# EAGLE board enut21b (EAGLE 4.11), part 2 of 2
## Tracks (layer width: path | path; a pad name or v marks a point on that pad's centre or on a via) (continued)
PE3 (continued)
  Top 0.152: IC1.5 32.01,50.77 37.6,56.36 37.6,70.15 36.86,70.89 J5.42 36.86,72.72 35.54,74.04 35.54,75.41 36.76,76.63 62.06,76.63 63.35,75.33 63.35,71.6 62.67,70.91 62.67,61.54 63.28,60.93 64.72,60.93 65.72,59.93 JP1.5
PE4
  Top 0.152: IC1.6 31.97,51.57 37.22,56.81 37.22,69.92 35.39,71.75 35.39,72.89 34.32,73.96 J5.43
PE5  (via drill 0.4)
  Top 0.152: J5.44 34.32,72.21 36.84,69.69 36.84,57.2 32.01,52.37 IC1.7 29.92,52.37 v29.29,52.93 | v39.5,45.23 38.89,45.23 38.13,44.47 R2.1
  Bottom 0.152: v29.29,52.93 30.74,52.93 38.13,45.54 38.44,45.23 v39.5,45.23
PE6  (via drill 0.4)
  Top 0.152: 32.05,53.17 IC1.8 30.19,53.17 29.67,53.69 28.83,53.69 v28.38,53.23 | 32.05,53.17 36.45,57.58 36.45,69.39 34.55,71.29 33.79,71.29 33.1,71.98 33.1,72.82 31.78,74.14 J5.45 | 32.05,53.17 32.05,53.23
  Bottom 0.152: v28.38,53.23 29.06,53.92 30.51,53.92 36.91,47.52 38.59,47.52 40.42,45.69 40.42,44.78 40.04,44.39 R31*.1
PE7  (via drill 0.4)
  Top 0.152: IC1.9 32.24,53.97 36.07,57.81 36.07,69.16 34.32,70.91 32.95,70.91 | 32.95,70.91 32.92,70.91 | 32.95,70.91 31.78,72.08 J5.46 31.78,72.77 30.51,74.04 30.51,75.41 32.19,77.08 64.88,77.08 66.09,75.86 66.09,68.02 67.09,67.03 v67.09,66.11
  Bottom 0.152: v67.09,66.11 67.09,63.67 66.4,62.99 64.88,62.99 63.82,61.93 JP1.8
PEN\
  Top 0.152: R4.1 33.69,48.26 33,47.57 IC1.1
PF0  (via drill 0.4)
  Top 0.152: IC1.61 v26.83,47.02
  Bottom 0.152: v26.83,47.02 26.83,46.93 26.85,46.91 23.65,43.71 12.15,43.71 6.38,49.48 J6.5
PF1  (via drill 0.4)
  Top 0.152: IC1.60 | IC1.60 | IC1.60 26.01,45.59 v26.01,47.67
  Bottom 0.152: v26.01,47.67 26.01,46.91 23.27,44.17 12.37,44.17 7.65,48.89 7.65,50.72 6.38,51.99 J6.7
PF2  (via drill 0.4)
  Top 0.152: IC1.59 25.23,45.67 v25.23,47.21
  Bottom 0.152: v25.23,47.21 25.23,47.08 25.25,47.06 22.81,44.62 12.6,44.62 8.11,49.12 8.11,53.31 6.89,54.53 6.43,54.53 J6.9
PF3  (via drill 0.4)
  Top 0.152: IC1.58 24.43,45.67 v24.43,47.61
  Bottom 0.152: v24.43,47.61 24.43,47.46 24.41,47.44 24.41,46.91 22.59,45.08 12.83,45.08 8.56,49.35 8.56,55.47 6.91,57.12 J6.11
PF4  (via drill 0.4)
  Top 0.152: 23.63,45.47 | 23.63,45.47 IC1.57 23.65,45.59 23.65,47.19 | 23.63,45.47 23.65,45.46 | 23.65,47.19 23.65,47.21 | 23.65,47.19 v23.63,47.17 | 23.63,45.47 23.63,41.1 v22.66,40.13 | RN30*.4 20.28,35.19 v20.3,35.1
  Bottom 0.152: v23.63,47.17 23.63,47.01 23.65,46.98 22.2,45.54 13.06,45.54 9.02,49.58 9.02,57.25 6.63,59.63 6.41,59.63 J6.13 | J7.1 11.46,26.64 11.46,28.62 12.07,29.23 15.5,29.23 JP5.8 19.08,32.81 19.08,34.34 19.92,35.17 v20.3,35.1 20.3,37.38 22.66,39.75 v22.66,40.13
PF5  (via drill 0.4)
  Top 0.152: 22.81,47.59 v22.83,47.57 22.83,45.67 IC1.56 22.89,45.52 22.89,41.42 v22.66,41.19 | JP5.10 18.09,33.82 18.09,34.87 18.68,35.46 RN30*.2
  Bottom 0.152: v22.83,47.57 22.83,47.38 22.81,47.37 22.81,46.83 21.98,45.99 13.29,45.99 9.48,49.8 9.48,59.41 6.74,62.15 6.43,62.15 J6.15 | J7.5 14.74,30.45 JP5.10 | JP5.10 18.1,33.81 JP5.10 | JP5.10 18.09,35.94 21.82,39.67 21.82,40.36 v22.66,41.19
PF6  (via drill 0.4)
  Top 0.152: v22.03,47.13 IC1.55 22.05,45.56 v22.05,42.03
  Bottom 0.152: v22.03,47.13 22.03,47.12 21.37,46.45 13.52,46.45 9.94,50.03 9.94,61.56 6.76,64.74 J6.17 | JP5.5 21.21,30.95 21.21,37.46 23.5,39.75 23.5,41.5 22.97,42.03 v22.05,42.03
PF7  (via drill 0.4)
  Top 0.152: IC1.54 | IC1.54 21.23,40.34 22.13,39.44 v26.85,39.44 | IC1.54 v21.23,47.61
  Bottom 0.152: v21.23,47.61 20.53,46.91 13.75,46.91 10.39,50.26 10.39,61.92 7.88,64.44 7.88,65.78 J6.19 | JP5.2 19.08,26.81 19.08,28.54 19.31,28.77 24.72,28.77 26.85,30.91 v26.85,39.44
POE+
  Top 0.61: JP3.3 81.95,20.65 J1.8 84.46,19.65 84.46,18.41 | 84.46,18.41 84.46,18.38 | J1.7 84.54,18.41 84.46,18.41
POE-
  Bottom 0.61: JP3.2 75.23,16.73 79.81,16.73 81.95,14.6 J1.4 83.19,15.82 84.46,15.82 J1.5
RAMSEL\  (via drill 0.4)
  Top 0.152: 52.68,39.98 | IC4.22 52.68,39.98 | IC3.6 41.58,61.92 v40.04,61.92 | 52.61,39.98 | IC4.22 52.61,39.98 | v39.65,48.97 40.34,48.28 43.69,48.28 52,39.98 52.53,39.98 | 52.53,39.98 | 52.53,39.98 IC4.22
  Bottom 0.152: v40.04,61.92 39.65,61.92 39.2,61.46 39.2,53.54 37.67,52.02 37.67,50.95 v39.65,48.97
RD\  (via drill 0.4)
  Top 0.152: IC3.3 41.52,64.36 v39.5,64.36 | IC1.34 16.74,58.77 17.48,58.03 21.44,58.03 24.11,55.37 24.11,54.76 24.72,54.15 v24.72,54 | IC2.31 47.79,24.57 47.81,24.58 48.65,24.58 49.03,24.96 v49.41,24.96 | IC4.24 52.76,42.49 v54.59,42.49 | 41.79,64.36 41.78,64.37 IC3.3 | v59.47,64.51 59.01,64.51 55.96,67.56 52.61,67.56 46.97,61.92 44.3,61.92 42.7,63.52 42.7,64.05 42.4,64.36 41.71,64.36 41.7,64.37 IC3.3
  Bottom 0.152: v39.5,64.36 38.36,63.22 38.36,60.4 32.8,54.83 28.15,54.83 27.31,54 v24.72,54 | J5.13 72.42,74.19 71.05,72.82 71.05,71.6 70.59,71.14 69.45,71.14 66.02,67.71 60.84,67.71 59.47,66.34 v59.47,64.51 59.47,63.29 58.09,61.92 58.09,60.32 57.64,59.86 56.65,59.86 56.27,59.48 56.27,57.73 55.66,57.12 55.66,43.56 v54.59,42.49 54.21,42.49 51.08,39.37 51.08,27.4 49.41,25.73 v49.41,24.96
RDYRTN\
  Top 0.152: IC2.46 41.03,27.41 41.18,27.55 41.63,27.55 42.01,27.93 RN1.5
RE485\
  Top 0.152: IC7.2 25.81,14.58 24.11,16.28 24.11,20.83 JP2.3 24.19,20.85 26.13,20.85 JP2.5
RESET  (via drill 0.4)
  Top 0.152: IC2.30 48.98,24.17 v49.1,24.05 | IC10.3 59.41,60.87 59.39,60.85 v59.39,59.71 59.7,59.41 62.21,59.41 62.51,59.1 62.51,57.04 64.27,57.04 64.72,56.59 64.72,55.14 65.03,54.83 66.7,54.83 68,56.13 68.46,56.13 68.5,56.17 IC6.1
  Bottom 0.152: 49.48,24.05 v49.1,24.05 50.02,24.05 52.46,26.49 52.46,38.3 58.55,44.39 58.55,55.52 57.94,56.13 57.94,58.11 58.63,58.8 59.01,58.8 59.39,59.18 v59.39,59.71
RESET\  (via drill 0.4)
  Top 0.152: v26.85,59.86 26.85,61.56 IC1.20 26.83,61.6 26.85,61.62 26.85,62.53 27.54,63.22 27.84,63.22 30.28,65.65 30.28,68.17 28.99,69.46 27.69,69.46 26.93,70.23 25.79,70.23 24.87,71.14 15.88,71.14 14.96,70.23 7.35,70.23 6.28,69.16 3.53,69.16 2.62,68.25 2.62,24.51 3.84,23.29 20.45,23.29 21.67,24.51 21.67,28.01 22.2,28.54 IC13.3 | IC10.1 61.3,61.15 61.3,61.31 v61.3,62.45 | v61.14,75.71 v61.14,65.81 | v68.61,67.18 IC6.18
  Bottom 0.152: v61.14,75.71 60.69,76.17 21.06,76.17 20.6,75.71 20.6,71.14 20.76,70.99 22.2,70.99 23.12,70.07 26.7,70.07 30.21,66.57 30.21,63.22 v26.85,59.86 | v68.61,67.18 67.09,67.18 66.78,66.87 62.21,66.87 v61.14,65.81 61.3,65.65 v61.3,62.45
RO  (via drill 0.4)
  Top 0.152: IC7.1 27.09,13.23 v28.45,13.23
  Bottom 0.152: JP1.10 63.76,63.93 62.13,62.3 62.13,60.55 59.92,58.34 58.86,58.34 58.4,57.88 58.4,56.36 59.01,55.75 59.01,44.17 52.91,38.07 52.91,26.26 47.81,21.15 45.37,21.15 44.84,20.62 44.84,19.32 41.94,16.43 41.94,14.14 41.03,13.23 35.16,13.23 34.55,12.62 29.06,12.62 v28.45,13.23
RRCUP
  Top 0.152: R12.2 52.1,22.4 52.08,22.37 50.83,23.62 C13.2 50.83,23.69 50.86,23.67 49.88,22.69 R13.2
RS485A
  Top 0.152: J4.2 | JP6.6 10.62,15.21 J4.2 | 21.33,15.82 IC7.6 22.61,15.85 23.04,16.28 23.04,18.87 22.28,19.63 12.3,19.63 JP6.10
  Bottom 0.152: 11.31,18.64 11.31,18.63 JP6.10 10.16,17.49 10.16,15.67 JP6.6
RS485B
  Top 0.152: IC7.7 20.51,14.58 R24.1 19.08,15.85 17.81,17.11 15.27,17.11 13.75,15.59 12.24,15.59 JP6.8 7.43,16.57 6.28,17.72 5.29,17.72 5.26,17.75 J4.1
RSHI
  Top 0.152: IC6.9 78.77,56.26 78.75,56.28 78.75,57.27 78.75,57.73 80.75,59.73 RN2.8
RSHIELD  (via drill 0.4)
  Top 0.406: C26.2 84.54,66.01 v84.54,65.05 84.54,64.11 C25.2 | C24.2 84.61,57.75 v84.61,56.74 84.61,55.85 C27.2
  Bottom 0.406: R32*.2 93.98,39.2 v93.98,40.81
  pour Ground (isolate 0.813): 97.19,67.91 97.19,47.59 91.47,47.59 91.47,43.15 97.19,43.15 97.19,38.7 83.85,38.7 83.85,67.91
  pour Bottom (isolate 0.813): 83.85,67.91 97.19,67.91 97.19,47.59 91.47,47.59 91.47,43.15 97.19,43.15 97.19,38.7 83.85,38.7
RSHIF  (via drill 0.4)
  Top 0.152: C24.1 81.76,58.53 82.33,59.1 83.24,59.1 83.58,59.44 RN2.1 84.52,59.73 v84.69,59.71
  Bottom 0.152: J3.7 86.75,54.68 85.68,55.75 85.68,58.57 v84.69,59.71
RSHO
  Top 0.152: IC6.8 77.5,56.33 77.53,56.36 77.53,57.27 77.53,57.65 80.4,60.53 RN2.7
RSHOF
  Top 0.152: C27.1 81.76,55.1 82.33,54.53 85.37,54.53 | 85.37,54.53 85.37,60.02 84.86,60.53 RN2.2 | 85.37,54.53 85.37,53.46 86.9,51.94 J3.8
RSRXD
  Top 0.152: IC6.14 73.69,65.86 73.72,65.88 73.72,66.8 74.86,67.94 79.66,67.94 80.34,67.25 80.34,62 81.01,61.33 RN2.6
RSRXDF
  Top 0.152: C26.1 81.76,66.91 82.17,67.33 84.92,67.33 85.37,66.87 85.37,61.77 84.92,61.31 | J3.3 86.59,53.31 86.14,53.77 86.14,60.09 84.92,61.31 | RN2.3 84.9,61.33 84.92,61.31
RSTXD
  Top 0.152: IC6.15 72.42,66.8 74.02,68.4 79.89,68.4 80.8,67.48 80.8,62.38 81.05,62.13 RN2.5
RSTXDF  (via drill 0.4)
  Top 0.152: C25.1 81.76,63.33 82.33,62.76 83.24,62.76 83.58,62.42 RN2.4 84.52,62.13 v84.69,62.15
  Bottom 0.152: J3.2 86.75,56.05 86.14,56.66 86.14,60.62 84.61,62.15 v84.69,62.15
RXD
  Top 0.152: IC6.13 74.96,65.48 75.01,65.43 75.01,64.59 74.55,64.13 67.62,64.13 65.82,65.93 JP1.11
SA14  (via drill 0.4)
  Top 0.152: IC4.3 42.02,50.41 42.47,50.72 42.47,52.78 44.23,52.78 45.14,51.79 v47.12,51.79 | IC3.36 49.63,66.64 v47.35,64.36
  Bottom 0.152: v47.35,64.36 47.43,63.14 45.52,61.23 45.52,55.52 46.59,54.45 46.59,52.32 v47.12,51.79
SA15
  Top 0.152: IC4.31 | IC4.31 52.73,51.46 | IC3.34 51.73,68.17 56.88,68.17 60.99,64.05 60.99,63.37 60.46,62.84 59.62,62.84 58.7,61.92 58.7,60.02 58.4,59.71 58.4,56.59 57.79,55.98 57.79,52.59 57.26,52.05 53.83,52.05 53.33,51.56 52.91,51.56 52.76,51.41 | 52.76,51.41 | IC4.31 52.76,51.41
SA16  (via drill 0.4)
  Top 0.152: IC3.12 43.02,55.75 v41.63,55.75 | IC4.2 | v39.81,51.63 40.04,51.41 IC4.2
  Bottom 0.152: v39.81,51.63 41.63,53.46 v41.63,55.75
SA17
  Top 0.152: IC3.8 41.58,60.32 42.47,60.32 42.85,59.94 42.85,57.58 41.79,56.51 41.33,56.51 40.87,56.05 40.87,55.52 41.41,54.99 43.16,54.99 45.52,52.62 48.8,52.62 51.31,50.11 52.46,50.11 52.48,50.13 IC4.30 | IC4.30 52.76,50.11 | IC4.30 | IC4.30 52.68,50.19 | 52.61,50.11 52.63,50.13 IC4.30
SA18  (via drill 0.4)
  Top 0.152: IC3.7 40.34,61.16 40.04,60.85 v40.04,60.78 | IC4.1 41.28,52.7 v39.73,52.7
  Bottom 0.152: v39.73,52.7 40.04,53 v40.04,60.78
SHLD485
  Top 0.305: 11.31,12.58 11.35,12.58 12.3,11.63 14.43,11.63 15.27,10.79 15.96,10.79 15.98,10.77 R26.1
  Top 0.813: 11.31,12.58 11.31,12.54 | 11.31,12.58 JP6.4 | J4.3 11.31,12.67 11.31,12.58
TDI
  Top 0.152: J7.9 12.78,35.48 17.1,35.48 | JP5.1 19.08,24.81 17.56,24.81 17.1,25.27 17.1,35.48 | RN30*.1 17.74,36.12 17.1,35.48
TDO
  Top 0.152: JP5.6 19.08,30.81 19.08,34.34 19.48,34.74 RN30*.3
  Bottom 0.152: JP5.6 16.12,27.86 12.78,27.86 J7.3
TPI+
  Top 0.152: R11.1 56.43,16.06 56.42,16.05 55.81,16.05 54.97,16.89 54.97,19.78 54.04,20.71 R12.1 52.01,20.71 52,20.7 51.47,20.7 50.93,20.16 50.93,19.55 50.35,18.97 IC2.17
TPI-
  Top 0.152: 56.55,19.2 56.57,19.17 | 56.55,19.2 R10.1 | 56.55,19.2 56.49,19.25 55.96,19.25 55.66,19.55 55.66,20.09 54.21,21.54 51.31,21.54 49.88,20.1 R13.1 | R13.1 49.87,20.09 49.15,19.37 IC2.18 | R13.1
TPO+
  Top 0.152: IC2.14 49.9,17.77 50.7,16.96 53.45,16.96 55.12,15.29 55.12,8.66 55.73,8.05 56.57,8.05 56.55,8.02 R20.1 56.61,8.01 58.09,9.5 TR1.16
TPO-
  Top 0.152: 47.62,18.18 IC2.15 50.11,18.17 50.93,17.34 53.68,17.34 55.5,15.52 55.5,13.23 55.88,12.85 56.19,12.85 56.23,12.88 R15.1 57.3,12.88 58.09,12.09 58.93,12.09 59.01,12.01 59.03,12.04 TR1.14
TXD
  Top 0.152: IC6.12 76.23,66.8 76.92,67.48 79.43,67.48 79.89,67.03 79.89,62 76.23,58.34 68.23,58.34 65.82,55.93 JP1.1
VCC3  (via drill 0.4)
  Top 0.152: v74.33,6.98 R28.2
  Top 0.406: 66.09,37.77 66.08,37.75 66.07,37.75 | 62.16,42.57 62.21,42.57 | C36.+ 62.16,42.57 | v62.13,43.86 62.13,42.57 62.16,42.57 | FB3.1 53.3,29.84 v54.89,29.84 | FB5.2 59.09,55.21 | FB5.2 | v61.19,54.81 60.79,55.21 FB5.2 | v84.16,68.86 J5.2 J5.1
  Top 0.61: C35.1 66.07,37.75 IC9.3 63.85,38.18 63.85,40.61 v62.26,40.61 62.26,42.52 C36.+ | FB4.2 53.4,26.97 53.68,27.25 v54.89,27.25
  Bottom 0.152: v54.89,27.25 54.89,10.03 56.27,8.66 64.65,8.66 65.56,7.74 73.56,7.74 v74.33,6.98
  Bottom 0.406: v62.26,40.61 62.29,40.59 62.21,40.51 62.21,29.84 v54.89,29.84 v54.89,27.25 | v61.19,54.81 61.22,54.83 62.13,53.92 | v62.13,43.86 62.13,53.92 | 62.13,53.92 69.07,53.92 69.07,62.76 75.16,68.86 v84.16,68.86
VCC3N  (via drill 0.4)
  Top 0.152: IC2.77 31.65,20.16 31.2,20.16 31.04,20.31 C9.1 29.98,20.62 29.67,20.62 v29.35,20.48 | IC2.110 39.04,11.16 39.04,9.27 38.09,9.27 C15.1 | IC2.62 34.62,27.1 34.62,27.71 C6.1 | IC2.120 43.03,10.28 42.55,9.8 42.55,9.65 42.13,9.23 C16.1 | v41.25,28.24 40.65,28.24 C7.1 | C14.1 34.21,9 34.17,9.04 34.23,9.1 34.17,9.17 34.17,9.87 | IC2.44 41.83,25.07 v41.86,24.96 | C12.1 50.02,12.57 IC2.1 | C8.1 46.07,28.33 46.05,28.32 46.23,28.14 IC2.33 | IC2.85 31.03,16.97 31.03,16.73 | 31.03,16.73 31.03,16.57 32.23,16.57 | 32.23,16.57 | 32.23,16.57 IC2.86 | 31.03,16.73 31.04,16.73 | v30.21,16.73 31.03,16.73 | 34.17,9.87 33.83,9.87 IC2.97 33.83,11.27 33.83,12.07 33.33,12.57 IC2.96 | 34.17,9.87 34.23,9.87 IC2.98 | IC2.98 | 34.17,9.87 34.17,9.88 | RN1.1 43.63,30.81 43.62,30.83 43.61,30.82 RN1.2 RN1.3 | RN1.3 42.79,30.81 42.78,30.83 | RN1.3 42.03,30.81 42.02,30.83 42.01,30.82 RN1.4 41.39,30.81 v41.18,30.6 | 30.13,27.25 IC13.5 IC13.6
  Top 0.203: 50.01,12.33 50.02,12.31 | C12.1 50.01,12.33 | 50.01,12.33 49.79,12.54
  Top 0.305: C15.1 37.98,9.18 v37.98,8.05 | C16.1 42.09,9.18 v42.09,8.05 | C6.1 34.85,28.23 | C14.1 33.53,8.93 v32.95,8.58 | 31.96,28.54 32.1,28.4 C37.1 33.37,28.36 v33.48,28.24 | IC12.5 25.77,34.58 v26.01,34.34
  Top 0.406: C8.1 46.86,28.36 v47.35,28.85 48.37,29.87 FB3.2 | C12.1 50.01,12.1 50.02,12.09 v50.02,10.79 | C6.1 34.75,28.24 v33.48,28.24 | IC13.6 31.96,28.54
  pour Supply (isolate 0.305, no thermals): 22.89,36.8 26.7,36.8 26.7,31.08 53.37,31.08 53.37,24.1 43.21,24.1 43.21,11.4 50.83,11.4 50.83,1.24 35.59,1.24 35.59,7.59 28.61,7.59 28.61,27.27 22.89,27.27
VCC3X  (via drill 0.4)
  Top 0.152: 50.43,69.31 50.47,69.31 C40.1
  Top 0.406: IC3.35 50.43,69.31 50.43,69.57 50.64,69.78 | FB5.1 55.9,56.59 v56.88,56.59 | C40.1 50.78,69.82 v50.78,70.99 | v57.18,60.7 57,60.8 C41.1 55.45,60.8 55.43,60.78 55.05,60.78 54.63,60.37 IC3.26 | v45.9,53.31 45.67,53.54 45.67,54.44 C39.1 45.64,54.53 45.63,54.53 | 45.63,54.53 IC3.15 | 45.63,54.53 45.6,54.53
  pour Supply (isolate 0.305, rank 3): 41.3,71.72 57.81,71.72 57.81,54.58 50.83,54.58 50.83,49.5 41.3,49.5
VCC5  (via drill 0.4)
  Top 0.152: C28.1 67.15,53.78 67.16,53.77 67.09,53.69 v67.09,52.7 | R25.2 IC7.8 | RN30*.5 20.28,38.7 20.07,38.91 19.46,38.91 | 17.86,38.91 17.18,38.91 16.95,38.68 v16.95,37.92 | 17.86,38.91 18.7,38.91 | 18.7,38.91 19.46,38.91 | RN30*.8 17.86,38.14 17.86,38.91 | RN30*.7 18.7,38.14 18.7,38.91 | RN30*.6 19.46,38.14 19.46,38.91
  Top 0.305: IC11.5 29.89,33.66 v30.21,33.35 | IC5.5 | IC5.5 | v34.17,5.68 33.86,5.38 IC5.5
  Top 0.406: IC7.8 22.57,13.31 23.34,12.54 23.34,10.79 23.37,10.77 | 23.37,10.77 v23.37,9.34 | 23.37,10.77 C32.1 | IC6.17 69.88,67.73 C23.1 69.91,68.05 v69.91,69.16 | FB2.1 10.24,42.14 v10.24,40.81 | IC10.5 61.3,58.35 v61.3,57.12
  Top 0.61: IC9.1 65.11,33.27 v65.71,33.88 | FB1.1 38.77,46.94 38.74,46.91 v38.74,46.15 | IC4.32 54.48,52.67 54.64,52.83 | 54.64,52.83 C38.1 | v56.88,52.85 54.66,52.85 54.64,52.83
  Top 0.813: v64.19,48.2 62.92,48.2 62.9,48.23 C20.+ 62.1,48.23 62.1,46.8 63.4,45.5 C34.1 66.2,45.5 66.23,45.53 67.18,45.53 68.29,44.42 IC8.2
  other vias: 80.04,50.77 81.31,50.77 81.31,38.07 80.04,38.07 78.77,50.77 77.5,50.77 78.77,38.07 77.5,38.07
  pour Supply (isolate 0.305, rank 2): 59.09,77.44 86.39,77.44 86.39,68.55 81.31,68.55 81.31,24.73 54.64,24.73 54.64,32.35 27.97,32.35 27.97,38.07 21.62,38.07 21.62,26 27.34,26 27.34,6.32 34.32,6.32 34.32,1.24 0.67,1.24 0.67,41.24 12.73,41.24 12.73,38.7 37.5,38.7 37.5,48.23 52.1,48.23 52.1,53.31 59.09,53.31
  pour Top (isolate 0.305, rank 3, no thermals): 71.78,51.41 85.12,51.41 85.12,37.44 71.78,37.44
VCC5P  (via drill 0.4)
  Top 0.152: R4.2 35.54,50.08 v35.54,50.72
  Top 0.305: IC1.21 26.01,61.57 26.01,62.91 26.17,63.06 26.62,63.06 27.07,63.58 C3.1 27.07,64.14 27.01,64.21 27.01,65.19 v27.54,65.2 | IC1.52 19.63,44.64 18.57,43.58 C4.1 18.7,43.34 v18.7,42.03
  Top 0.406: FB1.2 38.59,50.64 v38.59,51.63
  pour Supply (isolate 0.305): 13.37,71.72 40.04,71.72 40.04,49.5 36.23,49.5 36.23,39.98 31.14,39.98 31.14,46.32 19.71,46.32 19.71,42.2 19.08,41.56 17.81,41.56 17.81,46.32 13.37,46.32
WR\  (via drill 0.4)
  Top 0.152: v39.5,62.76 IC3.5 41.78,62.77 41.79,62.76 42.85,62.76 44.15,61.46 47.05,61.46 52.68,67.1 55.5,67.1 58.93,63.67 v60.23,63.67 | IC1.33 16.63,59.57 17.71,58.49 21.75,58.49 25.41,54.83 v25.41,53.23 | IC2.32 47.65,24.97 47.66,24.96 48.42,24.96 50.17,26.72 v51.54,26.72 | 52.68,48.81 IC4.29 52.79,48.81 53.6,48.81 54.59,47.82 54.59,46.53 v56.34,44.78
  Bottom 0.152: v39.5,62.76 38.74,62 38.74,60.09 33.02,54.38 28.45,54.38 27.31,53.23 v25.41,53.23 | J5.14 72.42,72.05 71.05,70.68 69.75,70.68 66.32,67.25 61.07,67.25 60.23,66.42 v60.23,63.67 60.23,63.37 58.55,61.69 58.55,59.41 56.11,56.97 56.11,45 v56.34,44.78 56.11,44.55 56.11,42.79 51.54,38.22 v51.54,26.72
XTCK  (via drill 0.4)
  Top 0.152: IC3.11 40.58,57.97 39.88,57.27 39.88,54.22 37.37,51.71 37.37,45.46 33.41,41.5 v33.41,40.2 | JP5.7 21.46,33.19 28.68,33.19 29.52,32.35 32.95,32.35 33.25,32.66 33.25,34.11 v31.58,35.78
  Bottom 0.152: v31.58,35.78 32.19,36.39 32.19,38.98 v33.41,40.2
XTDI  (via drill 0.4)
  Top 0.152: 41.52,59.56 IC3.9 39.81,59.57 39.12,58.87 39.12,54.76 36.45,52.09 36.45,45.92 31.58,41.04 v31.58,40.2
  Bottom 0.152: JP5.3 21.26,26.64 26.78,26.64 31.12,30.98 31.12,34.41 30.59,34.95 30.59,39.21 v31.58,40.2
XTDO  (via drill 0.4)
  Top 0.152: 53.06,58.72 52.99,58.8 52.96,58.77 IC3.24 52.91,58.78 | 52.91,58.78 52.91,58.8 | 52.91,58.78 52.01,58.78 v51.16,59.71 | v46.36,41.73 45.14,41.73 44,40.59 40.34,40.59 39.04,41.88 36.3,41.88 v33.41,38.98
  Bottom 0.152: v51.16,59.71 51.62,59.18 51.62,45.99 47.35,41.73 v46.36,41.73 | v33.41,38.98 33.41,32.51 25.71,24.81 17.63,24.81 16.95,25.5 16.95,26.68 JP5.4
XTMS  (via drill 0.4)
  Top 0.152: 41.5,58.8 IC3.10 40.23,58.77 39.5,58.03 39.5,54.53 36.91,51.94 36.91,45.69 32.49,41.27 v32.49,40.81 | JP5.9 22.13,35.86 22.13,37.77 23.04,38.68 30.21,38.68 v31.42,37.46
  Bottom 0.152: v32.49,40.81 32.49,39.98 31.42,38.91 v31.42,37.46

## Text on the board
Top: 1
Supply: 2
Ground: 3
Bottom: R34 | R30 | 4 | R31 | R32 | (C) EGNITE | R33 | ETHERNUT 2.1 REV-B
tPlace: PORT D | PORT B | PORT E | ADDRESS | DATA | CONTROL | GND | PWR | 8 | 7 | 6 | CPLD | 5 | 4 | It's better | to burn out | 3 | 2 | www.egnite.de | RS 232 | than fade | 1 | away | S | R | 9V | JTAG | ETHERNET | B | A | S | 100BaseT | P | TRANSFORMER | LINK | ACTIV | POWER | RESET
tNames: 232 | SRAM | 485
Measures: 8.9 | 10.4 | grid 2.54 | 3.8 | 4.0 | 4.4 | 4.4 | 5.6 | 10.7 | 10.7 | 13.9 | grid 2.54 | 78.0 | 30.5 | grid 2.54 | 25.4 | 15.2 | 10.2 | 3.8 | 3.8 | d=3.0 | 3.8 | 19.1 | 4.0 | 98.0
